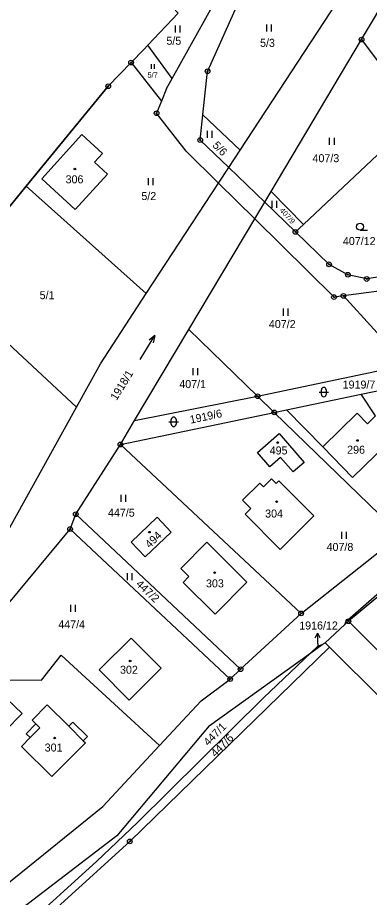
# Model space of a CAD drawing. Extents: x -445050 to -440454, y -1134563 to -1129741.
# Drawn here: x -442906.4 to -442831.5, y -1131200.4 to -1131013.5 of the extents above; entities that cross this region are included whole.
import ezdxf

# ---------------------------------------------------------------- set-up
doc = ezdxf.new("R2010")
doc.units = 0
for name, color, linetype in [('Vrstva 1', 7, 'Continuous'), ('Vrstva 13', 7, 'Continuous'), ('Vrstva 16', 7, 'Continuous'), ('Vrstva 18', 7, 'Continuous'), ('Vrstva 19', 7, 'Continuous'), ('Vrstva 24', 7, 'Continuous'), ('Vrstva 25', 7, 'Continuous'), ('Vrstva 3', 7, 'Continuous'), ('Vrstva 37', 7, 'Continuous'), ('Vrstva 4', 7, 'Continuous'), ('Vrstva 52', 7, 'Continuous')]:
    doc.layers.add(name, color=color, linetype=linetype)

msp = doc.modelspace()

# ---------------------------------------------------------------- linework, layer by layer
at = {"layer": 'Vrstva 1'}
for p, q in [((-442921.71, -1131154.07), (-442895.21, -1131122.14)), ((-442901.29, -1131154.25), (-442897.09, -1131148.93)), ((-442897.09, -1131148.93), (-442876.17, -1131168.15)), ((-442921.71, -1131154.07), (-442901.29, -1131154.25)), ((-442876.17, -1131168.15), (-442867.31, -1131158.65)), ((-442876.17, -1131168.15), (-442888.24, -1131181.08))]:
    msp.add_line(p, q, dxfattribs=at)
for points in [[(-442853.74, -1130997.43), (-442865.98, -1131024.86)], [(-442833.2, -1131018.12), (-442820.71, -1130997.18)], [(-442873.47, -1131026.38), (-442862.58, -1131006.79)], [(-442859, -1131041.59), (-442838.56, -1131010.38)], [(-442852.47, -1131050.42), (-442833.2, -1131018.12)], [(-442833.2, -1131018.12), (-442821.02, -1131034.39)], [(-442873.47, -1131026.38), (-442878.7, -1131019.3)], [(-442882.25, -1131023), (-442875.75, -1131031.18)], [(-442874.69, -1131028.55), (-442873.47, -1131026.38)], [(-442866.96, -1131034.11), (-442865.98, -1131024.86)], [(-442874.69, -1131028.55), (-442875.75, -1131031.18)], [(-442875.75, -1131031.18), (-442876.8, -1131033.77)], [(-442870.54, -1131041.82), (-442876.8, -1131033.77)], [(-442867.53, -1131039.47), (-442866.96, -1131034.11)], [(-442866.96, -1131034.11), (-442859, -1131041.59)], [(-442901.26, -1131047.68), (-442892.68, -1131038.31)], [(-442892.68, -1131038.31), (-442888.33, -1131042.3)], [(-442861.45, -1131045.33), (-442867.53, -1131039.47)], [(-442888.33, -1131042.3), (-442890.03, -1131044.16)], [(-442863.62, -1131048.64), (-442870.54, -1131041.82)], [(-442861.45, -1131045.33), (-442859, -1131041.59)], [(-442845.58, -1131057.41), (-442829.79, -1131042.61)], [(-442890.03, -1131044.16), (-442887.25, -1131046.71)], [(-442887.25, -1131046.71), (-442894.12, -1131054.22)], [(-442863.62, -1131048.64), (-442861.45, -1131045.33)], [(-442894.12, -1131054.22), (-442901.26, -1131047.68)], [(-442879, -1131072.11), (-442863.62, -1131048.64)], [(-442904.54, -1131049.3), (-442879, -1131072.11)], [(-442853.82, -1131052.68), (-442852.47, -1131050.42)], [(-442845.58, -1131057.41), (-442852.47, -1131050.42)], [(-442855.93, -1131056.22), (-442853.82, -1131052.68)], [(-442847.27, -1131058.99), (-442853.82, -1131052.68)], [(-442869.95, -1131079.74), (-442855.93, -1131056.22)], [(-442855.93, -1131056.22), (-442839.07, -1131072.85)], [(-442847.27, -1131058.99), (-442845.58, -1131057.41)], [(-442840.13, -1131065.88), (-442847.27, -1131058.99)], [(-442836.12, -1131068.08), (-442840.13, -1131065.88)], [(-442819.8, -1131067.07), (-442832.12, -1131068.99)], [(-442832.12, -1131068.99), (-442836.12, -1131068.08)], [(-442893.88, -1131096.24), (-442921.05, -1131070.95)], [(-442816.57, -1131069.86), (-442837.06, -1131072.58)], [(-442888.76, -1131087.02), (-442879, -1131072.11)], [(-442837.06, -1131072.58), (-442839.07, -1131072.85)], [(-442837.06, -1131072.58), (-442824.16, -1131086.73)], [(-442881.49, -1131099.09), (-442869.95, -1131079.74)], [(-442869.95, -1131079.74), (-442855.31, -1131093.9)], [(-442893.88, -1131096.24), (-442888.76, -1131087.02)], [(-442855.31, -1131093.9), (-442828.71, -1131088.3)], [(-442849.15, -1131096.78), (-442833.28, -1131093.46)], [(-442833.28, -1131093.46), (-442828.09, -1131092.38)], [(-442830.23, -1131098.05), (-442833.28, -1131093.46)], [(-442881.49, -1131099.09), (-442855.31, -1131093.9)], [(-442855.31, -1131093.9), (-442851.77, -1131097.33)], [(-442914.67, -1131133.71), (-442893.88, -1131096.24)], [(-442884.52, -1131104.16), (-442851.77, -1131097.33)], [(-442851.77, -1131097.33), (-442849.15, -1131096.78)], [(-442851.77, -1131097.33), (-442824.9, -1131123.33)], [(-442841.48, -1131104.63), (-442849.15, -1131096.78)], [(-442884.52, -1131104.16), (-442881.49, -1131099.09)], [(-442855.36, -1131105.84), (-442850.73, -1131101.85)], [(-442850.73, -1131101.85), (-442845.44, -1131107.97)], [(-442894.02, -1131118.98), (-442884.52, -1131104.16)], [(-442846.07, -1131140.04), (-442884.52, -1131104.16)], [(-442835.1, -1131111.16), (-442841.48, -1131104.63)], [(-442827.78, -1131104.01), (-442835.1, -1131111.16)], [(-442852.72, -1131108.9), (-442855.36, -1131105.84)], [(-442850.42, -1131106.92), (-442852.72, -1131108.9)], [(-442847.78, -1131109.98), (-442850.42, -1131106.92)], [(-442845.44, -1131107.97), (-442847.78, -1131109.98)], [(-442858.51, -1131116.01), (-442854.84, -1131112.35)], [(-442854.84, -1131112.35), (-442854.06, -1131113.12)], [(-442854.06, -1131113.12), (-442852.37, -1131111.43)], [(-442852.37, -1131111.43), (-442851.38, -1131112.42)], [(-442851.38, -1131112.42), (-442850.82, -1131111.86)], [(-442850.82, -1131111.86), (-442843.36, -1131119.35)], [(-442836.78, -1131142.43), (-442836.53, -1131141.86), (-442836.17, -1131141.47), (-442827.1, -1131133.55), (-442820.33, -1131127.68), (-442803.07, -1131113.14), (-442801.89, -1131112.71), (-442801.17, -1131112.96)], [(-442856.75, -1131117.77), (-442858.51, -1131116.01)], [(-442857.95, -1131118.97), (-442856.75, -1131117.77)], [(-442895.21, -1131122.14), (-442894.02, -1131118.98)], [(-442894.02, -1131118.98), (-442858.93, -1131151.9)], [(-442876.72, -1131119.63), (-442882.22, -1131124.88)], [(-442873.72, -1131122.78), (-442876.72, -1131119.63)], [(-442850.49, -1131126.45), (-442857.95, -1131118.97)], [(-442850.49, -1131126.45), (-442843.36, -1131119.35)], [(-442895.21, -1131122.14), (-442861.16, -1131154.02)], [(-442879.22, -1131128.02), (-442873.72, -1131122.78)], [(-442846.07, -1131140.04), (-442824.9, -1131123.33)], [(-442882.22, -1131124.88), (-442879.22, -1131128.02)], [(-442866.09, -1131124.92), (-442871.64, -1131130.49)], [(-442857.62, -1131133.44), (-442866.09, -1131124.92)], [(-442819.37, -1131127.99), (-442836, -1131141.72)], [(-442871.64, -1131130.49), (-442869.93, -1131132.2)], [(-442869.93, -1131132.2), (-442871.17, -1131133.45)], [(-442871.17, -1131133.45), (-442864.35, -1131140.2)], [(-442857.62, -1131133.44), (-442864.35, -1131140.2)], [(-442858.93, -1131151.9), (-442846.07, -1131140.04)], [(-442840.98, -1131146.27), (-442836.78, -1131142.43)], [(-442836.78, -1131142.43), (-442836, -1131141.72)], [(-442805.71, -1131171.98), (-442836, -1131141.72)], [(-442882.23, -1131145.3), (-442889.04, -1131152.06)], [(-442875.86, -1131151.72), (-442882.23, -1131145.3)], [(-442882.51, -1131188.49), (-442840.02, -1131147.23)], [(-442843.97, -1131148.42), (-442842.49, -1131147.04), (-442841.56, -1131146.68)], [(-442843.97, -1131148.42), (-442841.56, -1131146.68)], [(-442841.56, -1131146.68), (-442840.98, -1131146.27)], [(-442840.02, -1131147.23), (-442840.98, -1131146.27)], [(-442817.33, -1131169.74), (-442840.02, -1131147.23)], [(-442917.42, -1131217.39), (-442909.39, -1131210.5), (-442900.37, -1131202.55), (-442889.56, -1131192.74), (-442880.89, -1131184.45), (-442854.04, -1131157.97), (-442843.97, -1131148.42)], [(-442865.63, -1131163.96), (-442843.97, -1131148.42)], [(-442882.67, -1131158.48), (-442875.86, -1131151.72)], [(-442889.04, -1131152.06), (-442882.67, -1131158.48)], [(-442861.16, -1131154.02), (-442858.93, -1131151.9)], [(-442867.31, -1131158.65), (-442861.16, -1131154.02)], [(-442908.6, -1131158.27), (-442905.43, -1131161.35)], [(-442903.31, -1131162.71), (-442900.1, -1131159.48)], [(-442900.1, -1131159.48), (-442895.51, -1131164.02)], [(-442905.43, -1131161.35), (-442909, -1131165.02)], [(-442902.51, -1131163.49), (-442903.31, -1131162.71)], [(-442904.57, -1131165.61), (-442902.51, -1131163.49)], [(-442895.51, -1131164.02), (-442894.64, -1131163.14)], [(-442894.64, -1131163.14), (-442891.53, -1131166.22)], [(-442865.63, -1131163.96), (-442885.26, -1131187.31)], [(-442905.56, -1131168.36), (-442903.71, -1131166.45)], [(-442903.71, -1131166.45), (-442904.57, -1131165.61)], [(-442891.53, -1131166.22), (-442892.4, -1131167.1)], [(-442899.07, -1131174.67), (-442905.56, -1131168.36)], [(-442891.97, -1131167.56), (-442899.07, -1131174.67)], [(-442892.4, -1131167.1), (-442891.97, -1131167.56)], [(-442925.04, -1131210.79), (-442888.24, -1131181.08)], [(-442885.26, -1131187.31), (-442920.78, -1131214.44)], [(-442915.87, -1131218.74), (-442882.51, -1131188.49)]]:
    msp.add_lwpolyline(points, dxfattribs=at)
at = {"layer": 'Vrstva 13'}
for points in [[(-442872.21, -1131012.5), (-442878.7, -1131019.3)], [(-442879.56, -1131020.2), (-442882.25, -1131023)], [(-442878.7, -1131019.3), (-442879.56, -1131020.2)], [(-442882.25, -1131023), (-442887.1, -1131028.05)], [(-442887.1, -1131028.05), (-442904.54, -1131049.3)], [(-442904.54, -1131049.3), (-442917.86, -1131065.53)]]:
    msp.add_lwpolyline(points, dxfattribs=at)
at = {"layer": 'Vrstva 16'}
msp.add_line((-442842.42, -1131147.21), (-442842.61, -1131144.22), dxfattribs=at)
for points in [[(-442843.05, -1131145.25), (-442842.61, -1131144.22), (-442842.05, -1131145.18)], [(-442842.42, -1131147.22), (-442842.42, -1131147.21)]]:
    msp.add_lwpolyline(points, dxfattribs=at)
at = {"layer": 'Vrstva 24'}
for centre, radius in [((-442833.2, -1131018.12), 0.5), ((-442833.2, -1131018.12), 0.1), ((-442882.25, -1131023), 0.5), ((-442882.25, -1131023), 0.1), ((-442865.98, -1131024.86), 0.5), ((-442865.98, -1131024.86), 0.1), ((-442887.1, -1131028.05), 0.5), ((-442887.1, -1131028.05), 0.1), ((-442876.8, -1131033.77), 0.5), ((-442876.8, -1131033.77), 0.1), ((-442867.53, -1131039.47), 0.5), ((-442867.53, -1131039.47), 0.1), ((-442847.27, -1131058.99), 0.5), ((-442847.27, -1131058.99), 0.1), ((-442840.13, -1131065.88), 0.5), ((-442840.13, -1131065.88), 0.1), ((-442836.12, -1131068.08), 0.5), ((-442836.12, -1131068.08), 0.1), ((-442832.12, -1131068.99), 0.5), ((-442832.12, -1131068.99), 0.1), ((-442839.07, -1131072.85), 0.5), ((-442839.07, -1131072.85), 0.1), ((-442837.06, -1131072.58), 0.5), ((-442837.06, -1131072.58), 0.1), ((-442855.31, -1131093.9), 0.5), ((-442855.31, -1131093.9), 0.1), ((-442851.77, -1131097.33), 0.5), ((-442851.77, -1131097.33), 0.1), ((-442884.52, -1131104.16), 0.5), ((-442884.52, -1131104.16), 0.1), ((-442894.02, -1131118.98), 0.5), ((-442894.02, -1131118.98), 0.1), ((-442895.21, -1131122.14), 0.5), ((-442895.21, -1131122.14), 0.1), ((-442846.07, -1131140.04), 0.5), ((-442846.07, -1131140.04), 0.1), ((-442836, -1131141.72), 0.5), ((-442836, -1131141.72), 0.1), ((-442858.93, -1131151.9), 0.5), ((-442858.93, -1131151.9), 0.1), ((-442861.16, -1131154.02), 0.5), ((-442861.16, -1131154.02), 0.1), ((-442882.51, -1131188.49), 0.5), ((-442882.51, -1131188.49), 0.1)]:
    msp.add_circle(centre, radius, dxfattribs=at)
at = {"layer": 'Vrstva 25'}
for p, q in [((-442872.77, -1131016.63), (-442872.77, -1131015.13)), ((-442871.77, -1131016.63), (-442871.77, -1131015.13)), ((-442853.37, -1131016.4), (-442853.37, -1131014.9)), ((-442852.37, -1131016.4), (-442852.37, -1131014.9)), ((-442877.9, -1131024.33), (-442877.9, -1131023.32)), ((-442877.23, -1131024.33), (-442877.23, -1131023.32)), ((-442866, -1131039), (-442866, -1131037.5)), ((-442865, -1131039), (-442865, -1131037.5)), ((-442840, -1131040.47), (-442840, -1131038.97)), ((-442839, -1131040.47), (-442839, -1131038.97)), ((-442878.56, -1131049.04), (-442878.56, -1131047.54)), ((-442877.56, -1131049.04), (-442877.56, -1131047.54)), ((-442852.23, -1131053.87), (-442852.23, -1131052.37)), ((-442851.23, -1131053.87), (-442851.23, -1131052.37)), ((-442833.53, -1131058.63), (-442831.93, -1131058.63)), ((-442849.81, -1131076.79), (-442849.81, -1131075.29)), ((-442848.81, -1131076.79), (-442848.81, -1131075.29)), ((-442869.03, -1131089.42), (-442869.03, -1131087.92)), ((-442868.03, -1131089.42), (-442868.03, -1131087.92)), ((-442842.25, -1131093.03), (-442840.25, -1131093.03)), ((-442841.75, -1131093.53), (-442841.75, -1131092.53)), ((-442840.75, -1131092.53), (-442840.75, -1131093.53)), ((-442874.18, -1131099.34), (-442872.18, -1131099.34)), ((-442873.68, -1131099.84), (-442873.68, -1131098.84)), ((-442872.68, -1131098.84), (-442872.68, -1131099.84)), ((-442884.36, -1131116.36), (-442884.36, -1131114.86)), ((-442883.36, -1131116.36), (-442883.36, -1131114.86)), ((-442837.39, -1131124.21), (-442837.39, -1131122.71)), ((-442836.39, -1131124.21), (-442836.39, -1131122.71)), ((-442883.02, -1131133.01), (-442883.02, -1131131.51)), ((-442882.02, -1131133.01), (-442882.02, -1131131.51)), ((-442895.05, -1131139.75), (-442895.05, -1131138.25)), ((-442894.05, -1131139.75), (-442894.05, -1131138.25))]:
    msp.add_line(p, q, dxfattribs=at)
for points in [[(-442880.33, -1131086.11), (-442877.19, -1131081.01), (-442878.4, -1131082.02)], [(-442877.19, -1131081.01), (-442877.55, -1131082.55)]]:
    msp.add_lwpolyline(points, dxfattribs=at)
for centre, radius in [((-442894.2, -1131045.63), 0.175), ((-442833.53, -1131057.88), 0.75), ((-442834.08, -1131103.31), 0.175), ((-442851.04, -1131103.75), 0.175), ((-442851.27, -1131116.29), 0.175), ((-442878.33, -1131122.79), 0.175), ((-442864.46, -1131131.39), 0.175), ((-442882.44, -1131150.16), 0.175), ((-442898.5, -1131166.53), 0.175)]:
    msp.add_circle(centre, radius, dxfattribs=at)
for centre, start, end in [((-442841.25, -1131092.53), 0, 180), ((-442841.25, -1131093.53), 180, 0), ((-442873.18, -1131098.84), 0, 180), ((-442873.18, -1131099.84), 180, 0)]:
    msp.add_arc(centre, 0.5, start, end, dxfattribs=at)
at = {"layer": 'Vrstva 3'}
for points in [[(-442901.26, -1131047.68), (-442892.68, -1131038.31)], [(-442892.68, -1131038.31), (-442888.33, -1131042.3)], [(-442888.33, -1131042.3), (-442890.03, -1131044.16)], [(-442890.03, -1131044.16), (-442887.25, -1131046.71)], [(-442887.25, -1131046.71), (-442894.12, -1131054.22)], [(-442894.12, -1131054.22), (-442901.26, -1131047.68)], [(-442834.16, -1131097.48), (-442841.48, -1131104.63)], [(-442831.95, -1131099.74), (-442834.16, -1131097.48)], [(-442830.23, -1131098.05), (-442831.95, -1131099.74)], [(-442855.36, -1131105.84), (-442850.73, -1131101.85)], [(-442850.73, -1131101.85), (-442845.44, -1131107.97)], [(-442835.1, -1131111.16), (-442841.48, -1131104.63)], [(-442827.78, -1131104.01), (-442835.1, -1131111.16)], [(-442852.72, -1131108.9), (-442855.36, -1131105.84)], [(-442850.42, -1131106.92), (-442852.72, -1131108.9)], [(-442847.78, -1131109.98), (-442850.42, -1131106.92)], [(-442845.44, -1131107.97), (-442847.78, -1131109.98)], [(-442858.51, -1131116.01), (-442854.84, -1131112.35)], [(-442854.84, -1131112.35), (-442854.06, -1131113.12)], [(-442854.06, -1131113.12), (-442852.37, -1131111.43)], [(-442852.37, -1131111.43), (-442851.38, -1131112.42)], [(-442851.38, -1131112.42), (-442850.82, -1131111.86)], [(-442850.82, -1131111.86), (-442843.36, -1131119.35)], [(-442856.75, -1131117.77), (-442858.51, -1131116.01)], [(-442857.95, -1131118.97), (-442856.75, -1131117.77)], [(-442876.72, -1131119.63), (-442882.22, -1131124.88)], [(-442873.72, -1131122.78), (-442876.72, -1131119.63)], [(-442850.49, -1131126.45), (-442857.95, -1131118.97)], [(-442850.49, -1131126.45), (-442843.36, -1131119.35)], [(-442879.22, -1131128.02), (-442873.72, -1131122.78)], [(-442882.22, -1131124.88), (-442879.22, -1131128.02)], [(-442866.09, -1131124.92), (-442871.64, -1131130.49)], [(-442857.62, -1131133.44), (-442866.09, -1131124.92)], [(-442871.64, -1131130.49), (-442869.93, -1131132.2)], [(-442869.93, -1131132.2), (-442871.17, -1131133.45)], [(-442871.17, -1131133.45), (-442864.35, -1131140.2)], [(-442857.62, -1131133.44), (-442864.35, -1131140.2)], [(-442882.23, -1131145.3), (-442889.04, -1131152.06)], [(-442875.86, -1131151.72), (-442882.23, -1131145.3)], [(-442882.67, -1131158.48), (-442875.86, -1131151.72)], [(-442889.04, -1131152.06), (-442882.67, -1131158.48)], [(-442908.6, -1131158.27), (-442905.43, -1131161.35)], [(-442903.31, -1131162.71), (-442900.1, -1131159.48)], [(-442900.1, -1131159.48), (-442895.51, -1131164.02)], [(-442905.43, -1131161.35), (-442909, -1131165.02)], [(-442902.51, -1131163.49), (-442903.31, -1131162.71)], [(-442901.64, -1131164.33), (-442903.71, -1131166.45)], [(-442902.51, -1131163.49), (-442901.64, -1131164.33)], [(-442895.51, -1131164.02), (-442892.4, -1131167.1)], [(-442905.56, -1131168.36), (-442903.71, -1131166.45)], [(-442899.07, -1131174.67), (-442905.56, -1131168.36)], [(-442891.97, -1131167.56), (-442899.07, -1131174.67)], [(-442892.4, -1131167.1), (-442891.97, -1131167.56)]]:
    msp.add_lwpolyline(points, dxfattribs=at)
at = {"layer": 'Vrstva 37'}
for centre in [(-442894.2, -1131045.63), (-442834.08, -1131103.31), (-442851.04, -1131103.75), (-442851.27, -1131116.29), (-442878.33, -1131122.79), (-442864.46, -1131131.39), (-442882.44, -1131150.16), (-442898.5, -1131166.53)]:
    msp.add_circle(centre, 0.175, dxfattribs=at)
at = {"layer": 'Vrstva 4'}
for points in [[(-442861.45, -1131045.33), (-442853.82, -1131052.68)], [(-442855.93, -1131056.22), (-442863.62, -1131048.64)], [(-442834.16, -1131097.48), (-442841.48, -1131104.63)], [(-442831.95, -1131099.74), (-442834.16, -1131097.48)], [(-442830.23, -1131098.05), (-442831.95, -1131099.74)], [(-442901.64, -1131164.33), (-442903.71, -1131166.45)], [(-442902.51, -1131163.49), (-442901.64, -1131164.33)], [(-442895.51, -1131164.02), (-442892.4, -1131167.1)]]:
    msp.add_lwpolyline(points, dxfattribs=at)
at = {"layer": 'Vrstva 52'}
msp.add_lwpolyline([(-442914.32, -1131061.21), (-442904.54, -1131049.3), (-442887.1, -1131028.05), (-442882.25, -1131023), (-442879.56, -1131020.2), (-442878.7, -1131019.3), (-442872.21, -1131012.5), (-442882.23, -1131001.82)], dxfattribs=at)

# ---------------------------------------------------------------- texts
at = {"layer": 'Vrstva 16'}
msp.add_text('1918/1', height=1.7, rotation=58.306, dxfattribs=at).set_placement((-442885.33, -1131094.94))
msp.add_text('1916/12', height=1.7, dxfattribs=at).set_placement((-442846.47, -1131143.47))
at = {"layer": 'Vrstva 18'}
for s, height, p in [('5/5', 1.7, (-442874.72, -1131019.22)), ('5/3', 1.7, (-442854.8, -1131019.66)), ('5/7', 1.14, (-442878.75, -1131026.21)), ('407/3', 1.7, (-442843.64, -1131044.17)), ('5/2', 1.7, (-442880.05, -1131052.22)), ('407/12', 1.7, (-442837.18, -1131061.78)), ('5/1', 1.7, (-442901.69, -1131073.28)), ('407/2', 1.7, (-442852.93, -1131079.42)), ('407/1', 1.7, (-442871.99, -1131092.17)), ('1919/7', 1.7, (-442837.23, -1131092.27)), ('447/5', 1.7, (-442887.15, -1131119.49)), ('407/8', 1.7, (-442840.65, -1131126.78)), ('447/4', 1.7, (-442897.73, -1131143.23))]:
    msp.add_text(s, height=height, dxfattribs=at).set_placement(p)
for s, height, rotation, p in [('5/6', 1.7, 313.7814, (-442865.03, -1131040.72)), ('407/9', 1.14, 311.7823, (-442850.72, -1131054.48)), ('1919/6', 1.7, 11.8287, (-442869.56, -1131099.74)), ('447/2', 1.7, 316.8522, (-442881.34, -1131133.98)), ('1916/12', 0.1, 34.5085, (-442842.6, -1131147.35)), ('447/1', 1.7, 45.0231, (-442865.83, -1131168.32)), ('447/6', 1.7, 45.0182, (-442864.29, -1131170.69))]:
    msp.add_text(s, height=height, rotation=rotation, dxfattribs=at).set_placement(p)
at = {"layer": 'Vrstva 19'}
for s, p in [('306', (-442896.17, -1131048.66)), ('495', (-442852.75, -1131106.27)), ('296', (-442836.27, -1131106.12)), ('304', (-442853.72, -1131119.68)), ('303', (-442866.3, -1131134.52)), ('302', (-442884.59, -1131152.87)), ('301', (-442900.62, -1131169.4))]:
    msp.add_text(s, height=1.7, dxfattribs=at).set_placement(p)
msp.add_text('494', height=1.7, rotation=44.0145, dxfattribs=at).set_placement((-442878.29, -1131126.3))

doc.saveas('drawing.dxf')
